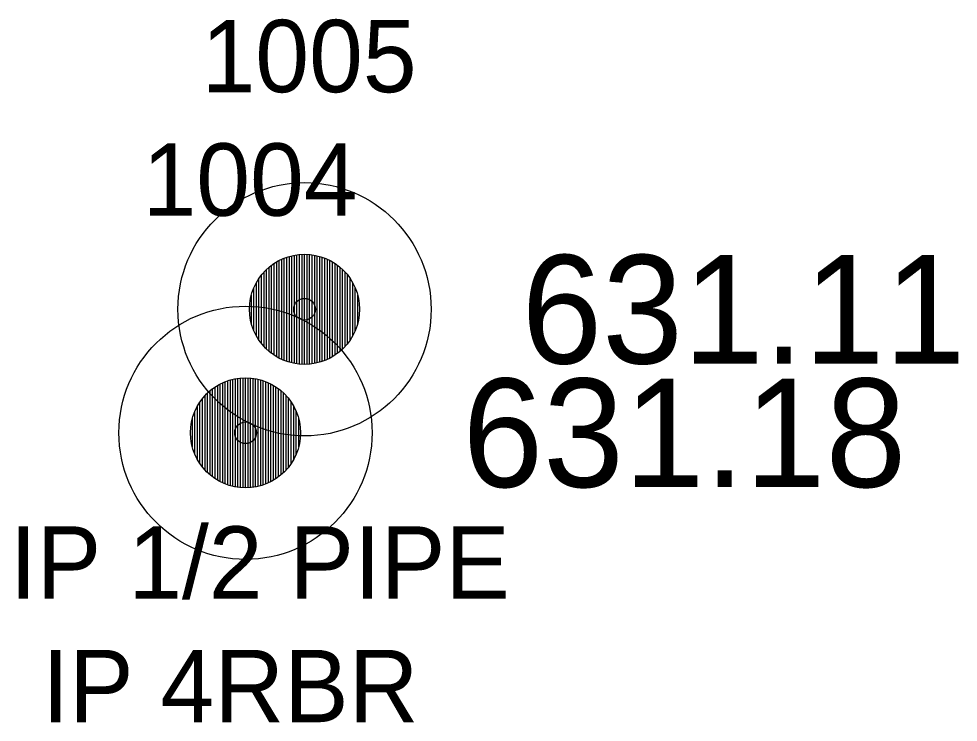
# Model space of a CAD drawing. Extents: x 1694813 to 1696862, y 1086485 to 1091027.
# Drawn here: x 1695865.05 to 1695878.04, y 1087333.51 to 1087343.23 of the extents above; entities that cross this region are included whole.
import ezdxf

# ---------------------------------------------------------------- set-up
doc = ezdxf.new("R2010")
doc.units = 0
for name, color, linetype in [('RD_EX_DV_Prop_txCode', 7, 'Continuous'), ('RD_EX_DV_PropPin', 7, 'Continuous'), ('RD_EX_TX_DV_Prop_ELEV', 7, 'Continuous'), ('RD_SMD_Locator', 7, 'Continuous')]:
    doc.layers.add(name, color=color, linetype=linetype)

msp = doc.modelspace()

# ---------------------------------------------------------------- linework, layer by layer
at = {"layer": 'RD_EX_DV_PropPin'}
for p, q in [((1695868.725, 1087338.504), (1695868.725, 1087339.919)), ((1695868.76, 1087338.491), (1695868.76, 1087339.932)), ((1695868.795, 1087338.48), (1695868.795, 1087339.943)), ((1695868.83, 1087338.471), (1695868.83, 1087339.952)), ((1695868.865, 1087338.464), (1695868.865, 1087339.96)), ((1695868.9, 1087338.458), (1695868.9, 1087339.966)), ((1695868.935, 1087338.454), (1695868.935, 1087339.97)), ((1695868.97, 1087338.452), (1695868.97, 1087339.972)), ((1695869.005, 1087338.451), (1695869.005, 1087339.973)), ((1695869.04, 1087338.452), (1695869.04, 1087339.972)), ((1695869.075, 1087338.454), (1695869.075, 1087339.97)), ((1695869.11, 1087338.458), (1695869.11, 1087339.966)), ((1695869.145, 1087338.464), (1695869.145, 1087339.96)), ((1695869.18, 1087338.471), (1695869.18, 1087339.952)), ((1695869.215, 1087338.48), (1695869.215, 1087339.943)), ((1695869.25, 1087338.491), (1695869.25, 1087339.932)), ((1695869.285, 1087338.504), (1695869.285, 1087339.919)), ((1695868.515, 1087338.63), (1695868.515, 1087339.794)), ((1695868.55, 1087338.602), (1695868.55, 1087339.822)), ((1695868.585, 1087338.577), (1695868.585, 1087339.846)), ((1695868.62, 1087338.555), (1695868.62, 1087339.868)), ((1695868.655, 1087338.536), (1695868.655, 1087339.887)), ((1695868.69, 1087338.519), (1695868.69, 1087339.905)), ((1695869.321, 1087338.519), (1695869.321, 1087339.905)), ((1695869.356, 1087338.536), (1695869.356, 1087339.887)), ((1695869.391, 1087338.555), (1695869.391, 1087339.868)), ((1695869.426, 1087338.577), (1695869.426, 1087339.846)), ((1695869.461, 1087338.602), (1695869.461, 1087339.822)), ((1695869.496, 1087338.63), (1695869.496, 1087339.794)), ((1695868.41, 1087338.738), (1695868.41, 1087339.686)), ((1695868.445, 1087338.697), (1695868.445, 1087339.727)), ((1695868.48, 1087338.661), (1695868.48, 1087339.763)), ((1695869.531, 1087338.661), (1695869.531, 1087339.763)), ((1695869.566, 1087338.697), (1695869.566, 1087339.727)), ((1695869.601, 1087338.738), (1695869.601, 1087339.686)), ((1695868.34, 1087338.842), (1695868.34, 1087339.581)), ((1695868.375, 1087338.785), (1695868.375, 1087339.638)), ((1695869.636, 1087338.785), (1695869.636, 1087339.638)), ((1695869.671, 1087338.842), (1695869.671, 1087339.581)), ((1695868.27, 1087339.016), (1695868.27, 1087339.408)), ((1695868.305, 1087338.914), (1695868.305, 1087339.51)), ((1695869.706, 1087338.914), (1695869.706, 1087339.51)), ((1695869.741, 1087339.016), (1695869.741, 1087339.408)), ((1695867.979, 1087336.774), (1695867.979, 1087338.237)), ((1695868.014, 1087336.765), (1695868.014, 1087338.246)), ((1695868.049, 1087336.757), (1695868.049, 1087338.253)), ((1695868.084, 1087336.751), (1695868.084, 1087338.259)), ((1695868.119, 1087336.747), (1695868.119, 1087338.263)), ((1695868.154, 1087336.745), (1695868.154, 1087338.265)), ((1695868.189, 1087336.744), (1695868.189, 1087338.266)), ((1695868.224, 1087336.745), (1695868.224, 1087338.265)), ((1695868.259, 1087336.747), (1695868.259, 1087338.263)), ((1695868.294, 1087336.751), (1695868.294, 1087338.259)), ((1695868.329, 1087336.757), (1695868.329, 1087338.253)), ((1695868.364, 1087336.765), (1695868.364, 1087338.246)), ((1695868.399, 1087336.774), (1695868.399, 1087338.237)), ((1695867.734, 1087336.895), (1695867.734, 1087338.115)), ((1695867.769, 1087336.871), (1695867.769, 1087338.14)), ((1695867.804, 1087336.849), (1695867.804, 1087338.162)), ((1695867.839, 1087336.83), (1695867.839, 1087338.181)), ((1695867.874, 1087336.812), (1695867.874, 1087338.198)), ((1695867.909, 1087336.798), (1695867.909, 1087338.213)), ((1695867.944, 1087336.785), (1695867.944, 1087338.226)), ((1695868.434, 1087336.785), (1695868.434, 1087338.226)), ((1695868.469, 1087336.798), (1695868.469, 1087338.213)), ((1695868.505, 1087336.812), (1695868.505, 1087338.198)), ((1695868.54, 1087336.83), (1695868.54, 1087338.181)), ((1695868.575, 1087336.849), (1695868.575, 1087338.162)), ((1695868.61, 1087336.871), (1695868.61, 1087338.14)), ((1695868.645, 1087336.895), (1695868.645, 1087338.115)), ((1695867.594, 1087337.031), (1695867.594, 1087337.979)), ((1695867.629, 1087336.99), (1695867.629, 1087338.02)), ((1695867.664, 1087336.954), (1695867.664, 1087338.056)), ((1695867.699, 1087336.923), (1695867.699, 1087338.087)), ((1695868.68, 1087336.923), (1695868.68, 1087338.087)), ((1695868.715, 1087336.954), (1695868.715, 1087338.056)), ((1695868.75, 1087336.99), (1695868.75, 1087338.02)), ((1695868.785, 1087337.031), (1695868.785, 1087337.979)), ((1695867.524, 1087337.136), (1695867.524, 1087337.875)), ((1695867.559, 1087337.079), (1695867.559, 1087337.932)), ((1695868.82, 1087337.079), (1695868.82, 1087337.932)), ((1695868.855, 1087337.136), (1695868.855, 1087337.875)), ((1695867.489, 1087337.207), (1695867.489, 1087337.803)), ((1695868.89, 1087337.207), (1695868.89, 1087337.803)), ((1695867.454, 1087337.309), (1695867.454, 1087337.701)), ((1695868.925, 1087337.309), (1695868.925, 1087337.701))]:
    msp.add_line(p, q, dxfattribs=at)
for centre, radius in [((1695869.005, 1087339.212), 1.75), ((1695869.005, 1087339.212), 0.761), ((1695868.189, 1087337.505), 1.75), ((1695868.189, 1087337.505), 0.761)]:
    msp.add_circle(centre, radius, dxfattribs=at)
at = {"layer": 'RD_SMD_Locator'}
for centre in [(1695869.005, 1087339.212), (1695868.189, 1087337.505)]:
    msp.add_circle(centre, 0.15, dxfattribs=at)

# ---------------------------------------------------------------- texts
at = {"layer": 'RD_EX_DV_Prop_txCode'}
for s, p in [('1005', (1695867.58, 1087342.212)), ('1004', (1695866.764, 1087340.505)), ('IP 1/2 PIPE', (1695864.931, 1087335.212)), ('IP 4RBR', (1695865.378, 1087333.505))]:
    msp.add_text(s, height=1, dxfattribs=at).set_placement(p)
at = {"layer": 'RD_EX_TX_DV_Prop_ELEV'}
for s, p in [('631.11', (1695872.005, 1087338.462)), ('631.18', (1695871.189, 1087336.755))]:
    msp.add_text(s, height=1.5, dxfattribs=at).set_placement(p)

doc.saveas('drawing.dxf')
